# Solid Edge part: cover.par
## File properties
Author: Robert a Rhodes jr
Template: NORMENG.PAR
Last saved by: Cadcim
Revision: 6
Application: Solid Edge
Accuracy: 0.99
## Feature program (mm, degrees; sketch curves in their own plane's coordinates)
sketch for "unnamed Protrusion 1" plane through (0, 0, 0) normal (0, 0, 1) x-axis (1, 0, 0)
  line (0, 0) -> (0, 0)
  circle centre (0, 0) radius 88.9
extrude "unnamed Protrusion 1" add finite 63.5 along -normal
fillet "Round_1" radius 25.4
thinwall "Thinwall_1"  Thickness = 6.35 mm
sketch for "ExtrudedProtrusion_3" #1 plane through (-1.5818, 0.3164, -63.5) normal (0, 0, -1) x-axis (-1, 0, 0)
  circle centre (-1.5818, 107.6336) radius 9.525
sketch for "ExtrudedProtrusion_3" #2 plane through (-1.5818, 0.3164, -63.5) normal (0, 0, -1) x-axis (-1, 0, 0)
  line (-20.6318, 86.5186) -> (-20.6318, 107.6336)
  arc centre (-1.5818, 107.6336) radius 19.05 from (-20.6318, 107.6336) to (17.4682, 107.6336) cw
  line (17.4682, 107.6336) -> (17.4682, 86.5186)
  arc centre (-1.5818, -0.3164) radius 88.9 from (17.4682, 86.5186) to (-20.6318, 86.5186) ccw
extrude "ExtrudedProtrusion_3" add finite 12.7 along -normal
pattern "unnamed Pattern 1" of "ExtrudedProtrusion_3"
extrude "unnamed Protrusion 2" add finite 12.7
extrude "unnamed Protrusion 3" add finite 12.7
sketch for "ExtrudedProtrusion_6" plane through (0, 0, 0) normal (0, 0, 1) x-axis (1, 0, 0)
  circle centre (0, 0) radius 31.75
extrude "ExtrudedProtrusion_6" add finite 19.05 along +normal
fillet "Round_2" radius 5.08
sketch used by "unnamed Cutout 1" plane through (0, 0, 0) normal (0, 0, 1) x-axis (1, 0, 0)
extrude "unnamed Cutout 1" cut through along -normal
pattern "unnamed Pattern 2" of "unnamed Cutout 1"
extrude "unnamed Cutout 2" cut through
extrude "unnamed Cutout 3" cut through
extrude "unnamed Cutout 4" cut through
extrude "unnamed Cutout 5" cut through
extrude "unnamed Cutout 6" cut through
extrude "unnamed Cutout 7" cut through
sketch for "unnamed Protrusion 4" plane through (0, 0, 0) normal (0, 0, -1) x-axis (0, -1, 0)
  circle centre (0, 0) radius 31.75
extrude "unnamed Protrusion 4" add along +normal
sketch for "Hole_1" plane through (0, 0, 19.05) normal (0, 0, 1) x-axis (1, 0, 0)
  hole centre (0, 0) bore radius 19.05
hole "Hole_1" diameter 38.1 through
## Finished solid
Body 1: solid body, 66 faces, 205 edges, 128 vertices.
  Faces by surface: plane 39, cylinder 24, torus 3
  Edges by curve: line 112, circle 69, intersection 24
Bounding box of the edges (mm; curved faces can reach further): 225.075 x 215.900 x 82.550, from (-112.5374, -88.9, -63.5) to (112.5374, 127, 19.05).
Cylindrical faces by radius (mm): R3.81 x14, R9.525 x3, R19.05 x4, R31.75 x1, R82.55 x1, R88.9 x1
Toroidal faces (ring radius, tube radius in mm): R26.67 r5.08 x1, R63.5 r19.05 x1, R63.5 r25.4 x1
Planar faces by outward normal: +x 12, +z 7, -x 12, -z 4, oblique 4
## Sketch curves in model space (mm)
arc centre (-45.72, -50.8, 0) radius 3.81 from (-41.91, -50.8, 0) through (-45.8329, -54.6083, 0) to (-49.53, -50.8, 0)
line (-49.53, -50.8, 0) -> (-49.53, 50.8, 0)
arc centre (-45.72, 50.8, 0) radius 3.81 from (-49.53, 50.8, 0) through (-45.6071, 54.6083, 0) to (-41.91, 50.8, 0)
line (-41.91, 50.8, 0) -> (-41.91, -50.8, 0)
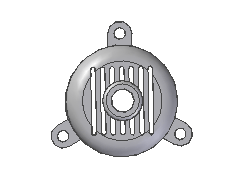
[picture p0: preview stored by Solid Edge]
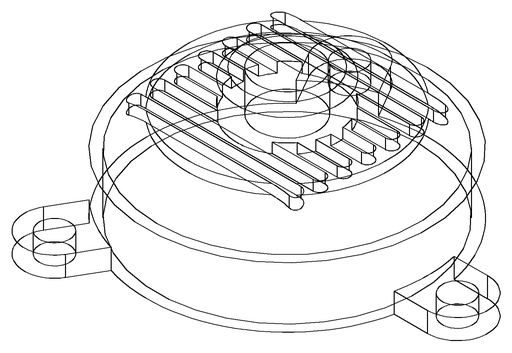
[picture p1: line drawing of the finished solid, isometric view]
